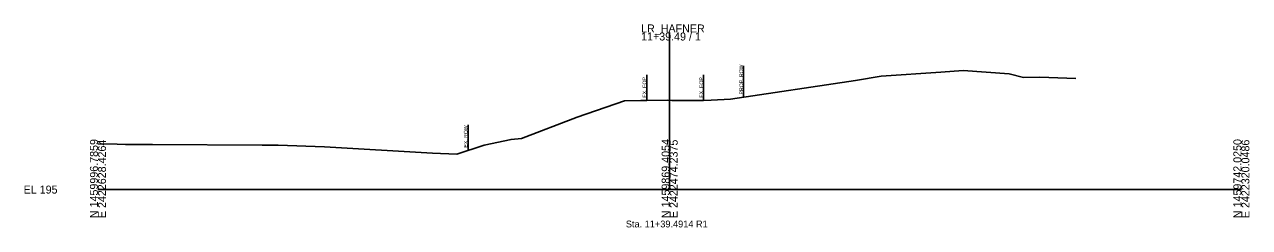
# Model space of a CAD drawing. Extents: x -26 to 403, y -13 to 3053.
# Drawn here: x -25.7 to 402.8, y -13.3 to 57.8 of the extents above; entities that cross this region are included whole.
import ezdxf

# ---------------------------------------------------------------- set-up
doc = ezdxf.new("R2010")
doc.units = 0
for name, color, linetype in [('8', 7, 'Continuous'), ('Draft_XS_Grid', 7, 'Continuous'), ('Draft_XS_Text', 7, 'Continuous'), ('DTM_X_GROUND', 7, 'Continuous'), ('ROW_LINES', 7, 'Continuous'), ('X_ROW', 7, 'Continuous'), ('X_ROW_TX', 7, 'Continuous'), ('X_TRANS_EOP', 7, 'Continuous'), ('XS_CELL', 7, 'Continuous')]:
    doc.layers.add(name, color=color, linetype=linetype)

msp = doc.modelspace()

# ---------------------------------------------------------------- linework, layer by layer
at = {"layer": 'DTM_X_GROUND'}
msp.add_lwpolyline([(0, 15.97), (6.74, 15.85), (9.61, 15.76), (10.23, 15.77), (11.87, 15.76), (19.03, 15.74), (57.39, 15.6), (63.03, 15.58), (79.27, 14.93), (116.98, 12.72), (125.59, 12.39), (135.14, 15.57), (144.51, 17.54), (148.19, 17.94), (167.6, 25.32), (184.22, 31.05), (184.25, 31.05), (189.97, 31.14), (192.02, 31.17), (199.35, 31.27), (200.74, 31.22), (201.19, 31.21), (206.07, 31.2), (211.89, 31.16), (214.51, 31.36), (221.27, 31.62), (265.04, 38.21), (274.01, 39.75), (294.88, 41.15), (302.63, 41.68), (318.78, 40.47), (323.78, 39.23), (329.49, 39.33), (342.04, 38.93)], dxfattribs=at)
at = {"layer": 'ROW_LINES'}
msp.add_line((225.88, 43.31), (225.88, 32.31), dxfattribs=at)
at = {"layer": 'X_ROW'}
msp.add_line((129.5, 22.7), (129.5, 13.7), dxfattribs=at)
at = {"layer": 'X_TRANS_EOP'}
for p, q in [((192.02, 40.17), (192.02, 31.17)), ((211.89, 40.16), (211.89, 31.16))]:
    msp.add_line(p, q, dxfattribs=at)
at = {"layer": 'XS_CELL'}
for p, q in [((200, 0), (200, 55)), ((0, 0), (200, 0)), ((200, 0), (400, 0))]:
    msp.add_line(p, q, dxfattribs=at)

# ---------------------------------------------------------------- texts
at = {"layer": '8'}
msp.add_text('X', height=0.012, dxfattribs=at).set_placement((51.38, 15.61))
at = {"layer": 'Draft_XS_Grid'}
msp.add_text('-', height=0.0001, dxfattribs=at).set_placement((0, 0))
at = {"layer": 'Draft_XS_Text'}
msp.add_text('Sta. 11+39.4914 R1', height=2.4, dxfattribs=at).set_placement((184.67, -13.25))
at = {"layer": 'ROW_LINES'}
msp.add_text('PROP. ROW', height=1.3, rotation=90, dxfattribs=at).set_placement((225.68, 33.31))
at = {"layer": 'X_ROW_TX'}
msp.add_text('EX. ROW', height=1.3, rotation=90, dxfattribs=at).set_placement((129.3, 14.7))
at = {"layer": 'X_TRANS_EOP'}
for p in [(191.82, 32.17), (211.69, 32.16)]:
    msp.add_text('EX. EOP', height=1.3, rotation=90, dxfattribs=at).set_placement(p)
at = {"layer": 'XS_CELL'}
for s, p in [('LR_HAFNER', (190, 55)), ('11+39.49 / 1', (190, 52.2)), ('EL 195', (-26, -1.4))]:
    msp.add_text(s, height=2.8, dxfattribs=at).set_placement(p)
for s, p in [('N 1459996.7859', (0, -10)), ('E 2422628.4264', (2.8, -10)), ('N 1459869.4054', (200, -10)), ('E 2422474.2375', (202.8, -10)), ('N 1459742.0250', (400, -10)), ('E 2422320.0486', (402.8, -10))]:
    msp.add_text(s, height=2.8, rotation=90, dxfattribs=at).set_placement(p)

doc.saveas('drawing.dxf')
